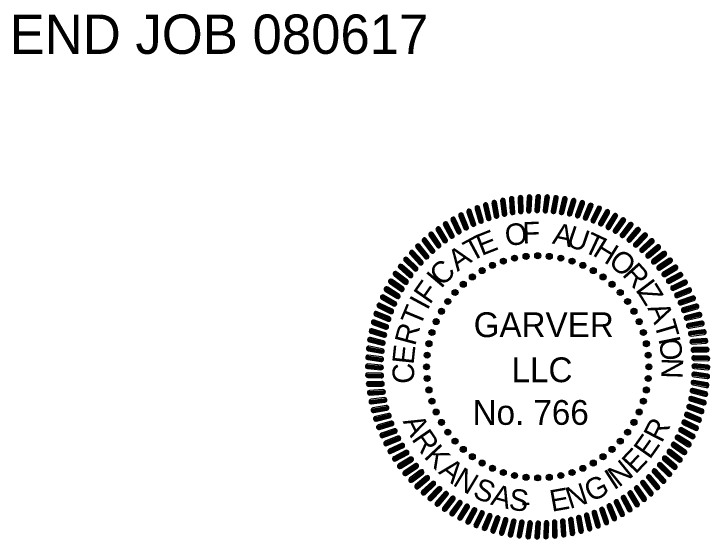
# Model space of a CAD drawing. Extents: x 1373884 to 1377798, y 1168424 to 1170626.
# Drawn here: x 1376197.1 to 1376674.2, y 1168442.7 to 1168802.9 of the extents above; entities that cross this region are included whole.
import ezdxf

# ---------------------------------------------------------------- set-up
doc = ezdxf.new("R2010")
doc.units = 0
doc.layers.add('G-ANNO-TEXT', color=7, linetype='Continuous')
doc.layers.add('R_Draft', color=7, linetype='Continuous')

# ---------------------------------------------------------------- blocks, each defined once
blk = doc.blocks.new('SEALDO')
at = {"layer": 'G-ANNO-TEXT'}
for radius in [0.0396, 0.0305, 0.0213, 0.0122, 0.00305]:
    blk.add_circle((1.403, -0.4559), radius, dxfattribs=at)
blk = doc.blocks.new('SEALRI')
at = {"layer": 'G-ANNO-TEXT'}
for p, q in [((-0.0226, 2.2583), (-0.0381, 2.0809)), ((-0.0083, 2.2815), (-0.0281, 2.0555)), ((0.0043, 2.2859), (-0.0164, 2.049)), ((0.0164, 2.2848), (-0.0043, 2.0479)), ((0.0281, 2.2783), (0.0083, 2.0523)), ((0.0226, 2.0756), (0.0381, 2.253))]:
    blk.add_line(p, q, dxfattribs=at)
for centre, start, end in [((0.0078, 2.2556), 355, 175), ((-0.0078, 2.0782), 175, 355)]:
    blk.add_arc(centre, 0.0305, start, end, dxfattribs=at)

msp = doc.modelspace()

# ---------------------------------------------------------------- block references
at = {"layer": 'G-ANNO-TEXT'}
for name, xscale, yscale, rotation in [('SEALRI', 51.6430967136, 51.64309671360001, 15.000000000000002), ('SEALRI', 51.643096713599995, 51.643096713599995, 12.000000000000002), ('SEALRI', 51.64309671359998, 51.64309671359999, 9.000000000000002), ('SEALRI', 51.64309671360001, 51.6430967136, 6.000000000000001), ('SEALRI', 51.64309671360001, 51.643096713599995, 3.0000000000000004), ('SEALRI', 51.64309671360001, 51.6430967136, -2.999999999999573), ('SEALRI', 51.64309671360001, 51.6430967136, -5.999999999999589), ('SEALRI', 51.643096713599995, 51.64309671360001, -8.999999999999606), ('SEALRI', 51.64309671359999, 51.64309671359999, -11.999999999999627), ('SEALRI', 51.6430967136, 51.64309671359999, -14.99999999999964), ('SEALRI', 51.64309671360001, 51.643096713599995, 20.99999999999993), ('SEALRI', 51.64309671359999, 51.64309671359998, 18.000000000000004), ('SEALRI', 51.643096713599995, 51.643096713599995, -17.999999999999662), ('SEALRI', 51.64309671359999, 51.64309671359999, -20.999999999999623), ('SEALRI', 51.64309671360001, 51.6430967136, 26.999999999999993), ('SEALRI', 51.6430967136, 51.643096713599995, 23.999999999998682), ('SEALRI', 51.643096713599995, 51.6430967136, -23.999999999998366), ('SEALRI', 51.643096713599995, 51.643096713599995, -26.99999999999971), ('SEALRI', 51.643096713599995, 51.643096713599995, 33), ('SEALRI', 51.6430967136, 51.64309671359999, 30.000000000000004), ('SEALRI', 51.6430967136, 51.643096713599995, -29.999999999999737), ('SEALRI', 51.6430967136, 51.6430967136, -32.999999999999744), ('SEALRI', 51.643096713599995, 51.64309671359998, 36), ('SEALRI', 51.643096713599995, 51.643096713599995, -35.999999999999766), ('SEALRI', 51.6430967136, 51.6430967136, 38.999999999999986), ('SEALRI', 51.64309671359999, 51.64309671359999, -38.99999999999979), ('SEALRI', 51.64309671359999, 51.64309671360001, 41.99999999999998), ('SEALRI', 51.6430967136, 51.643096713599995, -41.99999999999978), ('SEALRI', 51.643096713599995, 51.64309671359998, 44.999999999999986), ('SEALRI', 51.6430967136, 51.6430967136, -44.99999999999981), ('SEALRI', 51.643096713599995, 51.6430967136, 48), ('SEALDO', 51.64309671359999, 51.64309671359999, 119.99999999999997), ('SEALDO', 51.64309671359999, 51.64309671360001, 113.99999999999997), ('SEALDO', 51.643096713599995, 51.64309671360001, 107.99999999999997), ('SEALDO', 51.64309671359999, 51.64309671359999, 101.99999999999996), ('SEALDO', 51.64309671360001, 51.6430967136, 95.99999999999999), ('SEALRI', 51.6430967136, 51.643096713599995, -47.99999999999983), ('SEALRI', 51.643096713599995, 51.6430967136, 50.99999999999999), ('SEALDO', 51.6430967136, 51.643096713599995, 131.99999999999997), ('SEALDO', 51.6430967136, 51.6430967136, 125.99999999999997), ('SEALDO', 51.6430967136, 51.6430967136, 90), ('SEALDO', 51.64309671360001, 51.643096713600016, 83.99999999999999), ('SEALRI', 51.643096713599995, 51.6430967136, -50.99999999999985), ('SEALRI', 51.643096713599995, 51.64309671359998, 54.00000000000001), ('SEALDO', 51.643096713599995, 51.643096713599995, 138), ('SEALDO', 51.643096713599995, 51.6430967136, 77.99999999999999), ('SEALRI', 51.6430967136, 51.643096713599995, -53.99999999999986), ('SEALRI', 51.643096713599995, 51.6430967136, 56.999999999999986), ('SEALDO', 51.643096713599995, 51.643096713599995, 144), ('SEALDO', 51.64309671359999, 51.64309671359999, 72), ('SEALRI', 51.6430967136, 51.64309671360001, -56.999999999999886), ('SEALRI', 51.64309671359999, 51.64309671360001, 59.99999999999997), ('SEALDO', 51.6430967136, 51.64309671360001, 150), ('SEALDO', 51.6430967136, 51.6430967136, 66.00000000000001), ('SEALRI', 51.64309671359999, 51.64309671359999, -59.99999999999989), ('SEALRI', 51.64309671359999, 51.64309671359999, 63), ('SEALDO', 51.643096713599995, 51.6430967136, 156.00000000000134), ('SEALDO', 51.6430967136, 51.64309671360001, 60.00000000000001), ('SEALRI', 51.643096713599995, 51.6430967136, -62.99999999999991), ('SEALRI', 51.6430967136, 51.6430967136, 65.99999999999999), ('SEALDO', 51.643096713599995, 51.64309671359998, 54.00000000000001), ('SEALRI', 51.6430967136, 51.64309671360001, -65.99999999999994), ('SEALRI', 51.64309671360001, 51.6430967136, 68.99999999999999), ('SEALDO', 51.64309671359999, 51.6430967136, 162.00000000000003), ('SEALRI', 51.643096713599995, 51.6430967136, -68.99999999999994), ('SEALRI', 51.64309671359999, 51.64309671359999, 72), ('SEALDO', 51.64309671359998, 51.643096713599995, 168.00000000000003), ('SEALDO', 51.6430967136, 51.643096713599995, 48.00000000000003), ('SEALRI', 51.643096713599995, 51.6430967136, -71.99999999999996), ('SEALDO', 51.64309671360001, 51.6430967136, 174.00000000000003), ('SEALDO', 51.643096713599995, 51.6430967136, 42.00000000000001), ('SEALRI', 51.6430967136, 51.643096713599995, 75.00000000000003), ('SEALRI', 51.6430967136, 51.643096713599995, -74.99999999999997), ('SEALRI', 51.643096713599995, 51.643096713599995, 78.00000000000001), ('SEALDO', 51.6430967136, 51.6430967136, -179.99999999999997), ('SEALDO', 51.643096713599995, 51.64309671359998, 36), ('SEALRI', 51.643096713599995, 51.643096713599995, -78), ('SEALRI', 51.643096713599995, 51.64309671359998, 81), ('SEALRI', 51.64309671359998, 51.64309671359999, -81.00000000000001), ('SEALRI', 51.64309671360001, 51.6430967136, 84.00000000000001), ('SEALDO', 51.643096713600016, 51.64309671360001, -173.99999999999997), ('SEALDO', 51.6430967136, 51.64309671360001, 29.999999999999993), ('SEALRI', 51.64309671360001, 51.6430967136, -84.00000000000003), ('SEALDO', 51.643096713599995, 51.6430967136, -167.99999999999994), ('SEALDO', 51.6430967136, 51.643096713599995, 23.999999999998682), ('SEALRI', 51.6430967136, 51.6430967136, 87.00000000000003), ('SEALRI', 51.6430967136, 51.6430967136, -87.00000000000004), ('SEALRI', 51.6430967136, 51.6430967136, 90.00000000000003), ('SEALDO', 51.64309671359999, 51.64309671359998, -161.9999999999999), ('SEALDO', 51.64309671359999, 51.64309671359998, 18.000000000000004), ('SEALRI', 51.6430967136, 51.6430967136, -90.00000000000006), ('SEALRI', 51.64309671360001, 51.643096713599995, 93), ('SEALRI', 51.64309671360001, 51.6430967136, -93.00000000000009), ('SEALRI', 51.64309671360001, 51.643096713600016, 96.00000000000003), ('SEALDO', 51.6430967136, 51.6430967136, -156.00000000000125), ('SEALDO', 51.643096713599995, 51.643096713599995, 12.000000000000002), ('SEALRI', 51.643096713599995, 51.643096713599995, -96.0000000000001), ('SEALDO', 51.6430967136, 51.643096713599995, -149.99999999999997), ('SEALDO', 51.64309671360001, 51.6430967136, 6.000000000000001), ('SEALRI', 51.643096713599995, 51.643096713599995, 99.00000000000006), ('SEALRI', 51.6430967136, 51.6430967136, -99.00000000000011), ('SEALRI', 51.643096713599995, 51.643096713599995, 102.00000000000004), ('SEALDO', 51.64309671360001, 51.6430967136, -143.99999999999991), ('SEALRI', 51.643096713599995, 51.6430967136, -102.00000000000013), ('SEALRI', 51.6430967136, 51.643096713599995, 105.00000000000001), ('SEALDO', 51.6430967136, 51.6430967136, -137.9999999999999), ('SEALDO', 51.6430967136, 51.6430967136, -6.000000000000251), ('SEALRI', 51.64309671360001, 51.643096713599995, -105.00000000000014), ('SEALRI', 51.643096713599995, 51.6430967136, 108.00000000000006), ('SEALRI', 51.64309671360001, 51.643096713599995, -108.00000000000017), ('SEALRI', 51.64309671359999, 51.6430967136, 111.00000000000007), ('SEALDO', 51.643096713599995, 51.643096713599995, -131.99999999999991), ('SEALDO', 51.643096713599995, 51.643096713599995, -12.000000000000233), ('SEALRI', 51.643096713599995, 51.643096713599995, -111.00000000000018), ('SEALRI', 51.6430967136, 51.643096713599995, 114.00000000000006), ('SEALDO', 51.6430967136, 51.643096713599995, -125.9999999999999), ('SEALDO', 51.64309671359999, 51.6430967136, -18.00000000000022), ('SEALRI', 51.6430967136, 51.643096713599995, -114.0000000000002), ('SEALRI', 51.6430967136, 51.6430967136, 117.00000000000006), ('SEALRI', 51.64309671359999, 51.643096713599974, -117.00000000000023), ('SEALRI', 51.64309671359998, 51.643096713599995, 120.00000000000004), ('SEALDO', 51.64309671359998, 51.643096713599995, -119.99999999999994), ('SEALDO', 51.643096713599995, 51.64309671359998, -23.999999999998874), ('SEALRI', 51.6430967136, 51.643096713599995, -120.00000000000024), ('SEALRI', 51.643096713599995, 51.6430967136, 123.00000000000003), ('SEALDO', 51.6430967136, 51.64309671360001, -113.99999999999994), ('SEALDO', 51.64309671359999, 51.64309671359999, -30.00000000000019), ('SEALRI', 51.6430967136, 51.64309671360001, -123.00000000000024), ('SEALRI', 51.643096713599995, 51.6430967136, 126.00000000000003), ('SEALDO', 51.643096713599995, 51.6430967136, -107.99999999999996), ('SEALDO', 51.6430967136, 51.6430967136, -36.00000000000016), ('SEALRI', 51.643096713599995, 51.643096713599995, -126.00000000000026), ('SEALRI', 51.643096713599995, 51.6430967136, 129.00000000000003), ('SEALDO', 51.643096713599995, 51.64309671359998, -101.99999999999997), ('SEALDO', 51.6430967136, 51.64309671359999, -48.00000000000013), ('SEALDO', 51.643096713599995, 51.643096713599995, -42.00000000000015), ('SEALRI', 51.64309671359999, 51.64309671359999, -129.00000000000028), ('SEALRI', 51.643096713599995, 51.643096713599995, 132), ('SEALDO', 51.64309671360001, 51.6430967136, -96), ('SEALDO', 51.6430967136, 51.6430967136, -90.00000000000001), ('SEALDO', 51.643096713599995, 51.6430967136, -60.0000000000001), ('SEALDO', 51.643096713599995, 51.64309671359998, -54.00000000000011), ('SEALRI', 51.64309671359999, 51.64309671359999, -132.00000000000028), ('SEALRI', 51.64309671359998, 51.64309671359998, 135), ('SEALDO', 51.64309671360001, 51.6430967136, -84.00000000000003), ('SEALDO', 51.64309671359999, 51.64309671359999, -78.00000000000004), ('SEALDO', 51.643096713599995, 51.643096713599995, -72.00000000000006), ('SEALDO', 51.643096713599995, 51.6430967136, -66.00000000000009), ('SEALRI', 51.643096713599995, 51.643096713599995, -135.00000000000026), ('SEALRI', 51.643096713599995, 51.643096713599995, 138), ('SEALRI', 51.643096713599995, 51.643096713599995, 140.99999999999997), ('SEALRI', 51.64309671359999, 51.64309671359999, -141.0000000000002), ('SEALRI', 51.643096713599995, 51.64309671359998, -138.00000000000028), ('SEALRI', 51.643096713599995, 51.643096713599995, 144), ('SEALRI', 51.6430967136, 51.643096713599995, -144.00000000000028), ('SEALRI', 51.64309671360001, 51.6430967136, 146.99999999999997), ('SEALRI', 51.643096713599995, 51.6430967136, 149.99999999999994), ('SEALRI', 51.6430967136, 51.643096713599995, -150.00000000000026), ('SEALRI', 51.6430967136, 51.6430967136, -147.00000000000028), ('SEALRI', 51.64309671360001, 51.643096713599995, 152.99999999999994), ('SEALRI', 51.643096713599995, 51.643096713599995, -153.0000000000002), ('SEALRI', 51.6430967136, 51.64309671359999, 156.00000000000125), ('SEALRI', 51.643096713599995, 51.6430967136, 159), ('SEALRI', 51.64309671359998, 51.64309671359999, 161.99999999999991), ('SEALRI', 51.64309671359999, 51.64309671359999, -162.00000000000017), ('SEALRI', 51.6430967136, 51.64309671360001, -159.00000000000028), ('SEALRI', 51.6430967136, 51.6430967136, -156.00000000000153), ('SEALRI', 51.64309671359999, 51.64309671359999, 164.99999999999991), ('SEALRI', 51.643096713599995, 51.64309671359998, 167.99999999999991), ('SEALRI', 51.6430967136, 51.6430967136, 170.9999999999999), ('SEALRI', 51.643096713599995, 51.6430967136, 173.9999999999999), ('SEALRI', 51.643096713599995, 51.643096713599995, -174.00000000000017), ('SEALRI', 51.643096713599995, 51.6430967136, -171.00000000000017), ('SEALRI', 51.643096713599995, 51.6430967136, -168.0000000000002), ('SEALRI', 51.643096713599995, 51.64309671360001, -165.00000000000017), ('SEALRI', 51.64309671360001, 51.6430967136, 176.9999999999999), ('SEALRI', 51.6430967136, 51.6430967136, 179.99999999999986), ('SEALRI', 51.64309671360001, 51.6430967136, -177.00000000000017)]:
    msp.add_blockref(name, (1376556.04, 1168560.83), dxfattribs=dict(at, xscale=xscale, yscale=yscale, rotation=rotation))
at = {"layer": 'G-ANNO-TEXT', "xscale": 51.6430967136, "yscale": 51.6430967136}
for name in ['SEALRI', 'SEALDO']:
    msp.add_blockref(name, (1376556.04, 1168560.83), dxfattribs=at)

# ---------------------------------------------------------------- texts
at = {"layer": 'G-ANNO-TEXT'}
for s, rotation, p in [('O', 8.2771, (1376534.66, 1168643.42)), ('F', 1.6104, (1376545.85, 1168645.34)), ('A', 348.2771, (1376565.57, 1168645.47)), ('U', 341.2772, (1376574.8, 1168643.99)), ('E', 21.6104, (1376517.57, 1168636.77)), ('T', 334.9438, (1376586.4, 1168640.25)), ('T', 28.2771, (1376510.44, 1168632.6)), ('H', 328.2771, (1376593.04, 1168637.62)), ('A', 34.9438, (1376501.05, 1168625.81)), ('O', 319.7874, (1376603.72, 1168631.57)), ('C', 44.3881, (1376490.6, 1168615.41)), ('R', 311.9933, (1376613.39, 1168623.84)), ('I', 49.7408, (1376489.84, 1168613.9)), ('F', 54.9438, (1376482.16, 1168603.09)), ('I', 307.0081, (1376622.4, 1168613.72)), ('Z', 301.6104, (1376624.14, 1168611.94)), ('I', 61.6104, (1376480.4, 1168599.1)), ('T', 67.4314, (1376475.44, 1168587.67)), ('A', 292.9752, (1376631.09, 1168601.23)), ('T', 286.3085, (1376635.71, 1168590.54)), ('R', 74.9438, (1376471.99, 1168574.67)), ('I', 281.6104, (1376638.67, 1168580.16)), ('O', 276.4823, (1376639.24, 1168579.63)), ('E', 83.8985, (1376470.93, 1168562.05)), ('N', 268.2771, (1376641.08, 1168567.18)), ('C', 91.8842, (1376471.59, 1168549.45)), ('A', 296.5747, (1376463.39, 1168523.44)), ('R', 63.0959, (1376641.06, 1168508.13)), ('R', 304.6183, (1376469.21, 1168511.29)), ('E', 54.7309, (1376632.85, 1168496.81)), ('K', 313.3805, (1376477.51, 1168498.94)), ('E', 46.6807, (1376623.08, 1168486.73)), ('A', 321.2584, (1376487.48, 1168488.16)), ('N', 38.9821, (1376611.67, 1168477.71)), ('N', 329.1099, (1376497.18, 1168480)), ('I', 32.979, (1376608.26, 1168475.96)), ('G', 26.4132, (1376592.59, 1168467.73)), ('S', 337.6294, (1376510.81, 1168471.7)), ('N', 17.8686, (1376578.05, 1168463.22)), ('A', 345.4073, (1376523.23, 1168466.48)), ('S', 352.8046, (1376535.74, 1168462.96)), ('E', 10.0695, (1376565.7, 1168461.38)), ('-', 0.8385, (1376544.66, 1168461.04))]:
    msp.add_text(s, height=14.76, rotation=rotation, dxfattribs=at).set_placement(p)
for s, p in [('GARVER', (1376512.18, 1168581.21)), ('LLC', (1376538.17, 1168550.3)), ('No. 766', (1376511.44, 1168521.05))]:
    msp.add_text(s, height=17, dxfattribs=at).set_placement(p)
at = {"layer": 'R_Draft'}
msp.add_text('END JOB 080617', height=27, dxfattribs=at).set_placement((1376194.1, 1168775.46))

doc.saveas('drawing.dxf')
